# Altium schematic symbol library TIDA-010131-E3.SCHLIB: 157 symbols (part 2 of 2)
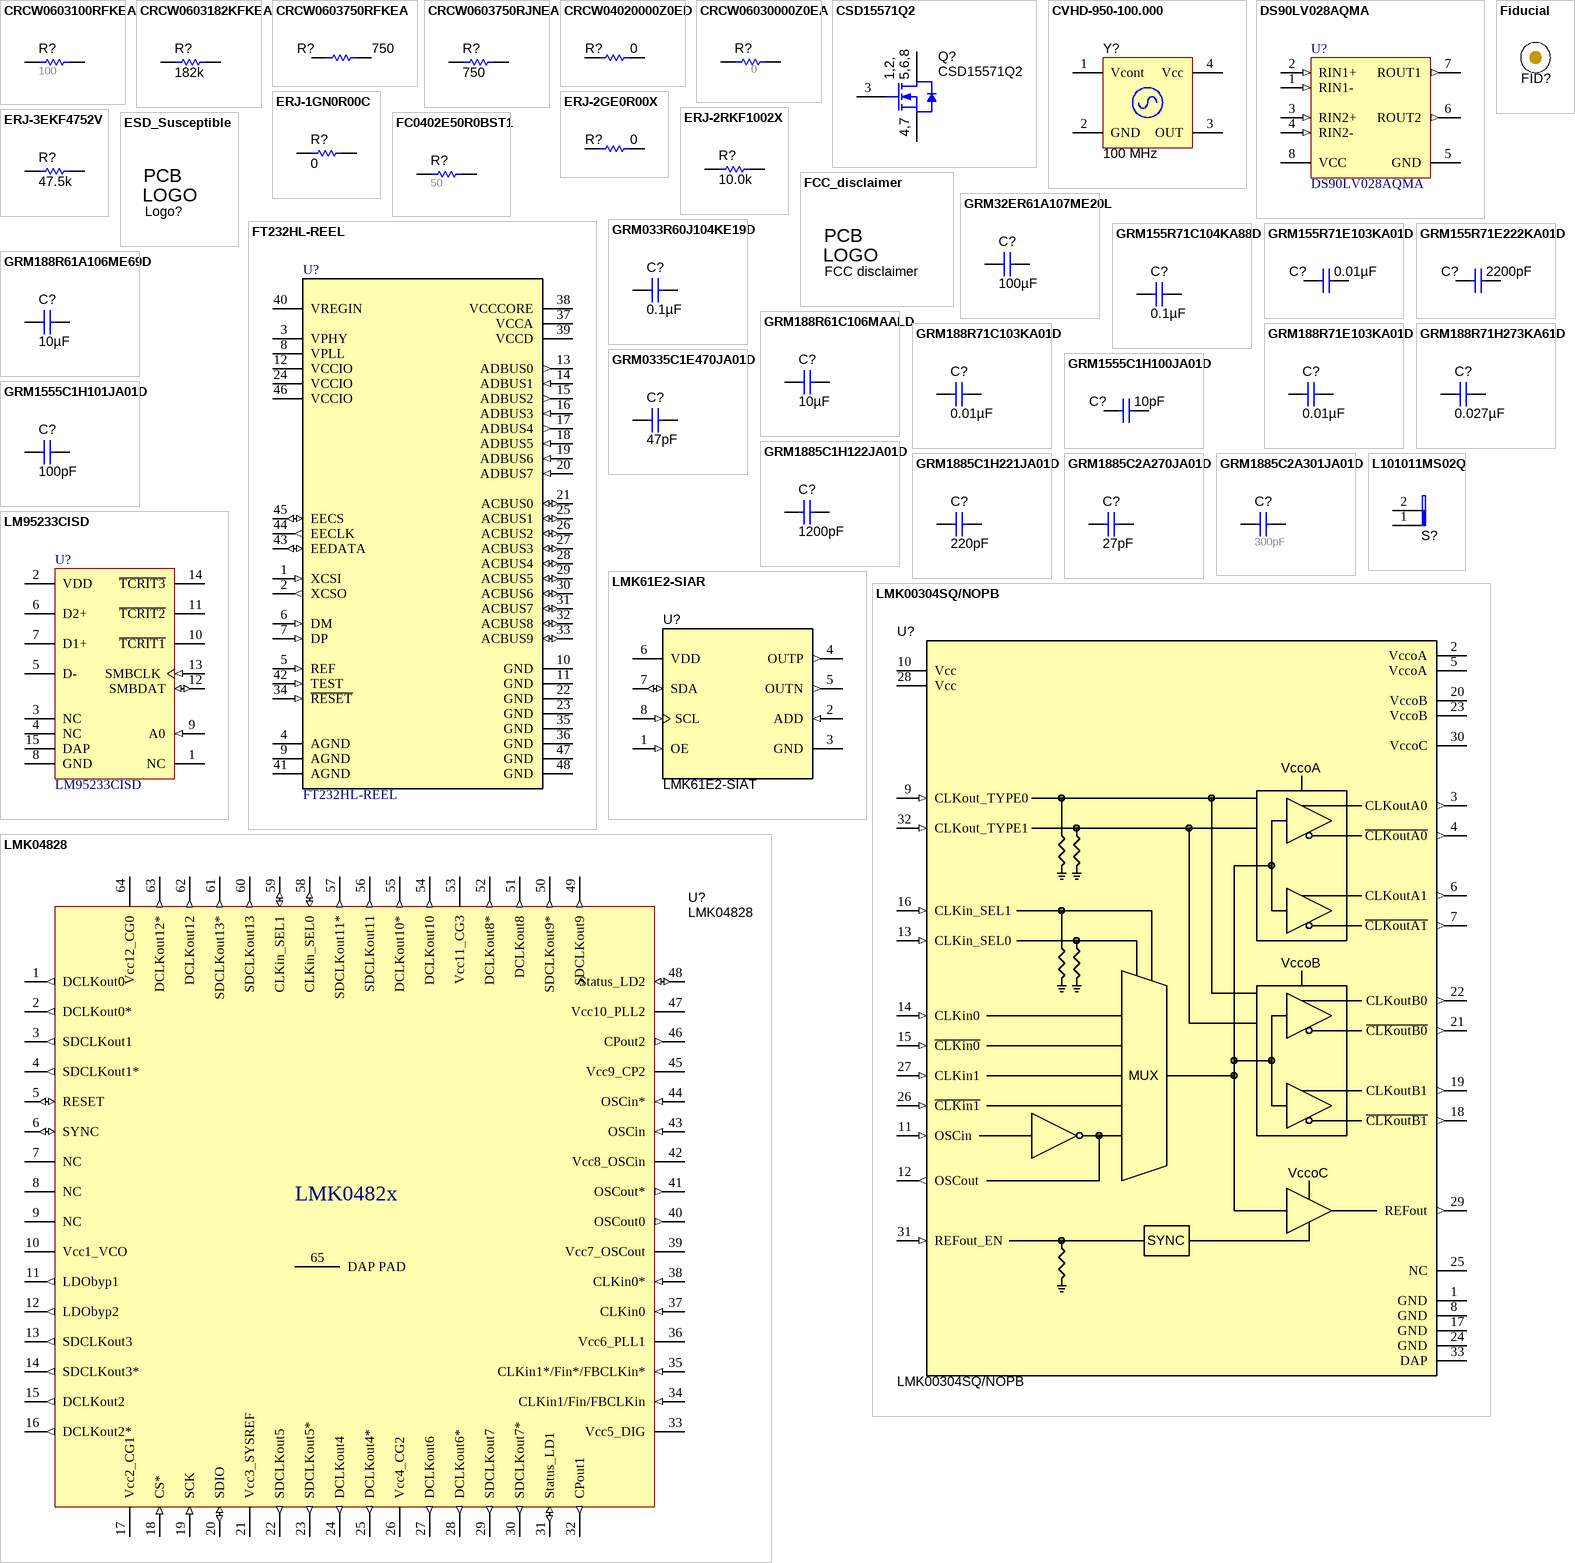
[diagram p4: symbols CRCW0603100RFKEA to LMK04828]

## GRM188R71E103KA01D
designator C?  ValueDisplayed: 0.01µF  (hidden comment: GRM188R71E103KA01D)
CAP, CERM, 0.01 µF, 25 V, +/- 10%, X7R, 0603; Manufacturer: MuRata; Polarized: N; CompType: Capacitor; Value: 0.01uF; U/M: EA; Cap_F: 0.00000001; Tolerance_%: 10; Value1: Unknown; VDC_V: 25; Value2: 25V; TaMin_C: -55; TaMax_C: 125; Cap_Case: 0603; SizeArea_mm2: 1.28; SizeAreaWB_mm2: 4.68; SizeX_mm: 1.6; SizeY_mm: 0.8; SizeZ_mm: 1; AEC Category: Q200
signal-integrity model Cap
simulation model Cap
footprint 0603
footprint 0603M
footprint 0603L
footprint 0603_HV
footprint 0603S
pins: 1, 2

## GRM188R71H273KA61D
designator C?  ValueDisplayed: 0.027µF  (hidden comment: GRM188R71H273KA61D)
CAP, CERM, 0.027 µF, 50 V, +/- 10%, X7R, 0603; Manufacturer: MuRata; Cap_Case: 0603; Polarized: N; TaMax_C: 125; TaMin_C: -55; Tolerance_%: 10; VDC_V: 50; Cap_F: 0.000000027; CompType: Capacitor; Value: 0.027uF; Value1: Unknown; Value2: 50V; U/M: EA; AEC Category: Q200; SizeArea_mm2: 1.28; SizeAreaWB_mm2: 4.68; SizeX_mm: 1.6; SizeY_mm: 0.8; SizeZ_mm: 1
signal-integrity model Cap
simulation model Cap
footprint 0603
footprint 0603M
footprint 0603L
footprint 0603_HV
footprint 0603S
pins: 1, 2

## GRM0335C1E470JA01D
designator C?  ValueDisplayed: 47pF  (hidden comment: GRM0335C1E470JA01D)
CAP, CERM, 47 pF, 25 V, +/- 5%, C0G/NP0, 0201; Manufacturer: MuRata; Polarized: N; CompType: Capacitor; Value: 47pF; U/M: EA; Cap_F: 0.000000000047; Tolerance_%: 5; Value1: Unknown; VDC_V: 25; Value2: 25V; TaMin_C: -55; TaMax_C: 125; Cap_Case: 0201; SizeArea_mm2: 0.18; SizeAreaWB_mm2: 2.08; SizeX_mm: 0.6; SizeY_mm: 0.3; SizeZ_mm: 0.33; AEC Category: Q200
signal-integrity model Cap
simulation model Cap
footprint 0201_033
footprint 0201_033M
footprint 0201_033L
pins: 1, 2

## GRM1555C1H100JA01D
designator C?  ValueDisplayed: 10pF  (hidden comment: GRM1555C1H100JA01D)
CAP, CERM, 10 pF, 50 V, +/- 5%, C0G/NP0, 0402; Manufacturer: MuRata; Polarized: N; CompType: Capacitor; Value: 10pF; U/M: EA; Cap_F: 0.00000000001; Tolerance_%: 5; Value1: Unknown; VDC_V: 50; Value2: 50V; TaMin_C: -55; TaMax_C: 125; Cap_Case: 0402; SizeArea_mm2: 0.5; SizeAreaWB_mm2: 3; SizeX_mm: 1; SizeZ_mm: 0.6; AEC Category: Q200
signal-integrity model Cap
simulation model Cap
footprint 0402
footprint 0402M
footprint 0402L
footprint 0402S
pins: 1, 2

## GRM1555C1H101JA01D
designator C?  ValueDisplayed: 100pF  (hidden comment: GRM1555C1H101JA01D)
CAP, CERM, 100 pF, 50 V, +/- 5%, C0G/NP0, 0402; Manufacturer: MuRata; Polarized: N; CompType: Capacitor; Value: 100pF; U/M: EA; Cap_F: 0.0000000001; Tolerance_%: 5; Value1: Unknown; VDC_V: 50; Value2: 50V; TaMin_C: -55; TaMax_C: 125; Cap_Case: 0402; SizeArea_mm2: 0.5; SizeAreaWB_mm2: 3; SizeX_mm: 1; SizeZ_mm: 0.6; AEC Category: Q200
signal-integrity model Cap
simulation model Cap
footprint 0402
footprint 0402M
footprint 0402L
footprint 0402S
pins: 1, 2

## GRM1885C1H122JA01D
designator C?  ValueDisplayed: 1200pF  (hidden comment: GRM1885C1H122JA01D)
CAP, CERM, 1200 pF, 50 V, +/- 5%, C0G/NP0, 0603; Manufacturer: MuRata; Cap_Case: 0603; Polarized: N; TaMax_C: 125; TaMin_C: -55; Tolerance_%: 5; VDC_V: 50; Cap_F: 0.0000000012; CompType: Capacitor; Value: 1200pF; Value1: Unknown; Value2: 50V; U/M: EA; SizeArea_mm2: 1.28; SizeAreaWB_mm2: 4.68; SizeX_mm: 1.6; SizeY_mm: 0.8; SizeZ_mm: 1; AEC Category: Q200
signal-integrity model Cap
simulation model Cap
footprint 0603
footprint 0603M
footprint 0603L
footprint 0603_HV
footprint 0603S
pins: 1, 2

## GRM1885C1H221JA01D
designator C?  ValueDisplayed: 220pF  (hidden comment: GRM1885C1H221JA01D)
CAP, CERM, 220 pF, 50 V, +/- 5%, C0G/NP0, 0603; Manufacturer: MuRata; Cap_Case: 0603; Polarized: N; TaMax_C: 125; TaMin_C: -55; Tolerance_%: 5; VDC_V: 50; Cap_F: 0.00000000022; CompType: Capacitor; Value: 220pF; Value1: Unknown; Value2: 50V; U/M: EA; AEC Category: Q200; SizeArea_mm2: 1.28; SizeAreaWB_mm2: 4.68; SizeX_mm: 1.6; SizeY_mm: 0.8; SizeZ_mm: 1
signal-integrity model Cap
simulation model Cap
footprint 0603
footprint 0603M
footprint 0603L
footprint 0603_HV
footprint 0603S
pins: 1, 2

## GRM1885C2A270JA01D
designator C?  ValueDisplayed: 27pF  (hidden comment: GRM1885C2A270JA01D)
CAP, CERM, 27 pF, 100 V, +/- 5%, C0G/NP0, 0603; Manufacturer: MuRata; Polarized: N; CompType: Capacitor; Value: 27pF; U/M: EA; Cap_F: 0.000000000027; Tolerance_%: 5; Value1: Unknown; VDC_V: 100; Value2: 100V; TaMin_C: -55; TaMax_C: 125; Cap_Case: 0603; SizeArea_mm2: 1.28; SizeAreaWB_mm2: 4.68; SizeX_mm: 1.6; SizeY_mm: 0.8; SizeZ_mm: 1; AEC Category: Q200
signal-integrity model Cap
simulation model Cap
footprint 0603
footprint 0603M
footprint 0603L
footprint 0603_HV
footprint 0603S
pins: 1, 2

## GRM1885C2A301JA01D
designator C?  ValueDisplayed: 300pF  (hidden comment: GRM1885C2A301JA01D)
CAP, CERM, 300pF, 100V, +/-5%, C0G/NP0, 0603; Manufacturer: MuRata; Cap_Case: 0603; Polarized: N; TaMax_C: 125; TaMin_C: -55; Tolerance_%: 5; VDC_V: 100; Cap_F: 0.0000000003; CompType: Capacitor; Value1: Unknown; U/M: EA
signal-integrity model Cap
simulation model Cap
footprint 0603
footprint 0603M
footprint 0603L
footprint 0603_HV
footprint 0603S
pins: 1, 2

## L101011MS02Q
designator S?  (value not drawn)
SWITCH SLIDE SPST 4A PCB, TH; Manufacturer: C&K Components; Symbol Creator: a0411947; VDC_V: 125; SwitchFunction: Off-On; PositionCount: 1; CurrentRating_mA: 4000
footprint SW_ L101011MS02Q (SWITCH SLIDE sPST 4A PCB)
pins: 1, 2

## LM95233CISD
designator U?
Dual Remote Diode and Local Temperature Sensor with SMBus Interface and TruTherm Technology, 15-pin LLP; Manufacturer: Texas Instruments; PackageTopMarking: NS*UZXYTT*95233CI; PowerWise: Y; CompType: Temp Sensor IC
footprint SDA14B (SON, 14-Leads, Body 4x4mm, Pitch 0.5mm, NSC Recommended)
pins: 1 NC, 2 VDD (power), 3 NC, 4 NC, 5 D-, 6 D2+, 7 D1+, 8 GND (power), 9 A0 (in), 10 ~{TCRIT1} (oc), 11 ~{TCRIT2} (oc), 12 SMBDAT (io), 13 SMBCLK (in), 14 ~{TCRIT3} (oc), 15 DAP (power)

## LMK61E2-SIAR
designator U?, comment LMK61E2-SIAT
Ultra-Low Jitter Programmable Oscillator with Internal EEPROM, SIA0008B; Manufacturer: Texas Instruments; SymbolCreator: Altium; CompType: IC; U/M: EA
footprint SIA0008B
pins: 1 OE (in), 2 ADD (in), 3 GND (power), 4 OUTP (out), 5 OUTN (out), 6 VDD (power), 7 SDA (io), 8 SCL (in)

## LMK00304SQ/NOPB
designator U?
3.1-GHz Differential Clock Buffer/Level Translator, RTV0032A (WQFN-32); Manufacturer: Texas Instruments; SymbolCreator: a0411947; SizeArea_mm2: 25; SizeAreaWB_mm2: 49; SizeX_mm: 5; SizeZ_mm: 0.8; CompType: IC; U/M: EA
footprint RTV0032A
pins: 1 GND (power), 2 VccoA (power), 3 CLKoutA0 (out), 4 ~{CLKoutA0} (out), 5 VccoA (power), 6 CLKoutA1 (out), 7 ~{CLKoutA1} (out), 8 GND (power), 9 CLKout_TYPE0 (in), 10 Vcc (power), 11 OSCin (in), 12 OSCout (out), 13 CLKin_SEL0 (in), 14 CLKin0 (in), 15 ~{CLKin0} (in), 16 CLKin_SEL1 (in), 17 GND (power), 18 ~{CLKoutB1} (out), 19 CLKoutB1 (out), 20 VccoB (power), 21 ~{CLKoutB0} (out), 22 CLKoutB0 (out), 23 VccoB (power), 24 GND (power), 25 NC, 26 ~{CLKin1} (in), 27 CLKin1 (in), 28 Vcc (power), 29 REFout (out), 30 VccoC (power), 31 REFout_EN (in), 32 CLKout_TYPE1 (in), 33 DAP (power)
1 alternate drawing of the same symbol

## LMK04828
designator U?
Manufacturer: Texas Instruments; PartNumber: LMK04828BISQ
footprint LLP64(NS_SQA64A)_HYBRID
footprint NKD0064A (QFN, 64-Leads, Body 9x9mm, Pitch 0.5mm)
pins: 1 DCLKout0 (out) "CG0", 2 DCLKout0* (out) "CG0", 3 SDCLKout1 (out) "CG0", 4 SDCLKout1* (out) "CG0", 5 RESET (io), 6 SYNC (io), 7 NC, 8 NC, 9 NC, 10 Vcc1_VCO (power) "VCC_VCO_LDO", 11 LDObyp1 (out), 12 LDObyp2 (out), 13 SDCLKout3 (out) "CG1", 14 SDCLKout3* (out) "CG1", 15 DCLKout2 (out) "CG1", 16 DCLKout2* (out) "CG1", 17 Vcc2_CG1 (power) "VCC_CG1", 18 CS* (in), 19 SCK (in) "CG2", 20 SDIO (io) "CG2", 21 Vcc3_SYSREF (power) "CG2", 22 SDCLKout5 (out) "CG2", 23 SDCLKout5* (out), 24 DCLKout4 (out) "VCC_Digital", 25 DCLKout4* (out), 26 Vcc4_CG2 (power), 27 DCLKout6 (out) "Status", 28 DCLKout6* (out), 29 SDCLKout7 (out), 30 SDCLKout7* (out), 31 Status_LD1 (io), 32 CPout1 (out), 33 Vcc5_DIG (power) "Status", 34 CLKin1/Fin/FBCLKin (in), 35 CLKin1*/Fin*/FBCLKin* (in) "VCC_CP1", 36 Vcc6_PLL1 (power), 37 CLKin0 (in), 38 CLKin0* (in) "VCC_OSCin", 39 Vcc7_OSCout (power), 40 OSCout0 (out), 41 OSCout* (out) "OSCout", 42 Vcc8_OSCin (power), 43 OSCin (in) "VCC_DIV", 44 OSCin* (in) "uWire", 45 Vcc9_CP2 (power) "Vcc_CP2", 46 CPout2 (out) "uWire", 47 Vcc10_PLL2 (power) "Vcc_PLL2", 48 Status_LD2 (io) "CG3", 49 SDCLKout9 (out) "CG3", 50 SDCLKout9* (out) "CG3", 51 DCLKout8 (out) "CG3", 52 DCLKout8* (out) "VCC_CG4", 53 Vcc11_CG3 (power) "CG4", 54 DCLKout10 (out) "CG4", 55 DCLKout10* (out) "CG4", 56 SDCLKout11 (out) "CG4", 57 SDCLKout11* (out) "VCC_CG5", 58 CLKin_SEL0 (io) "CG5", 59 CLKin_SEL1 (io) "CG5", 60 SDCLKout13 (out) "CG5", 61 SDCLKout13* (out) "CG5", 62 DCLKout12 (out) "Status", 63 DCLKout12* (out), 64 Vcc12_CG0 (power), 65 DAP PAD (power) "DAP"

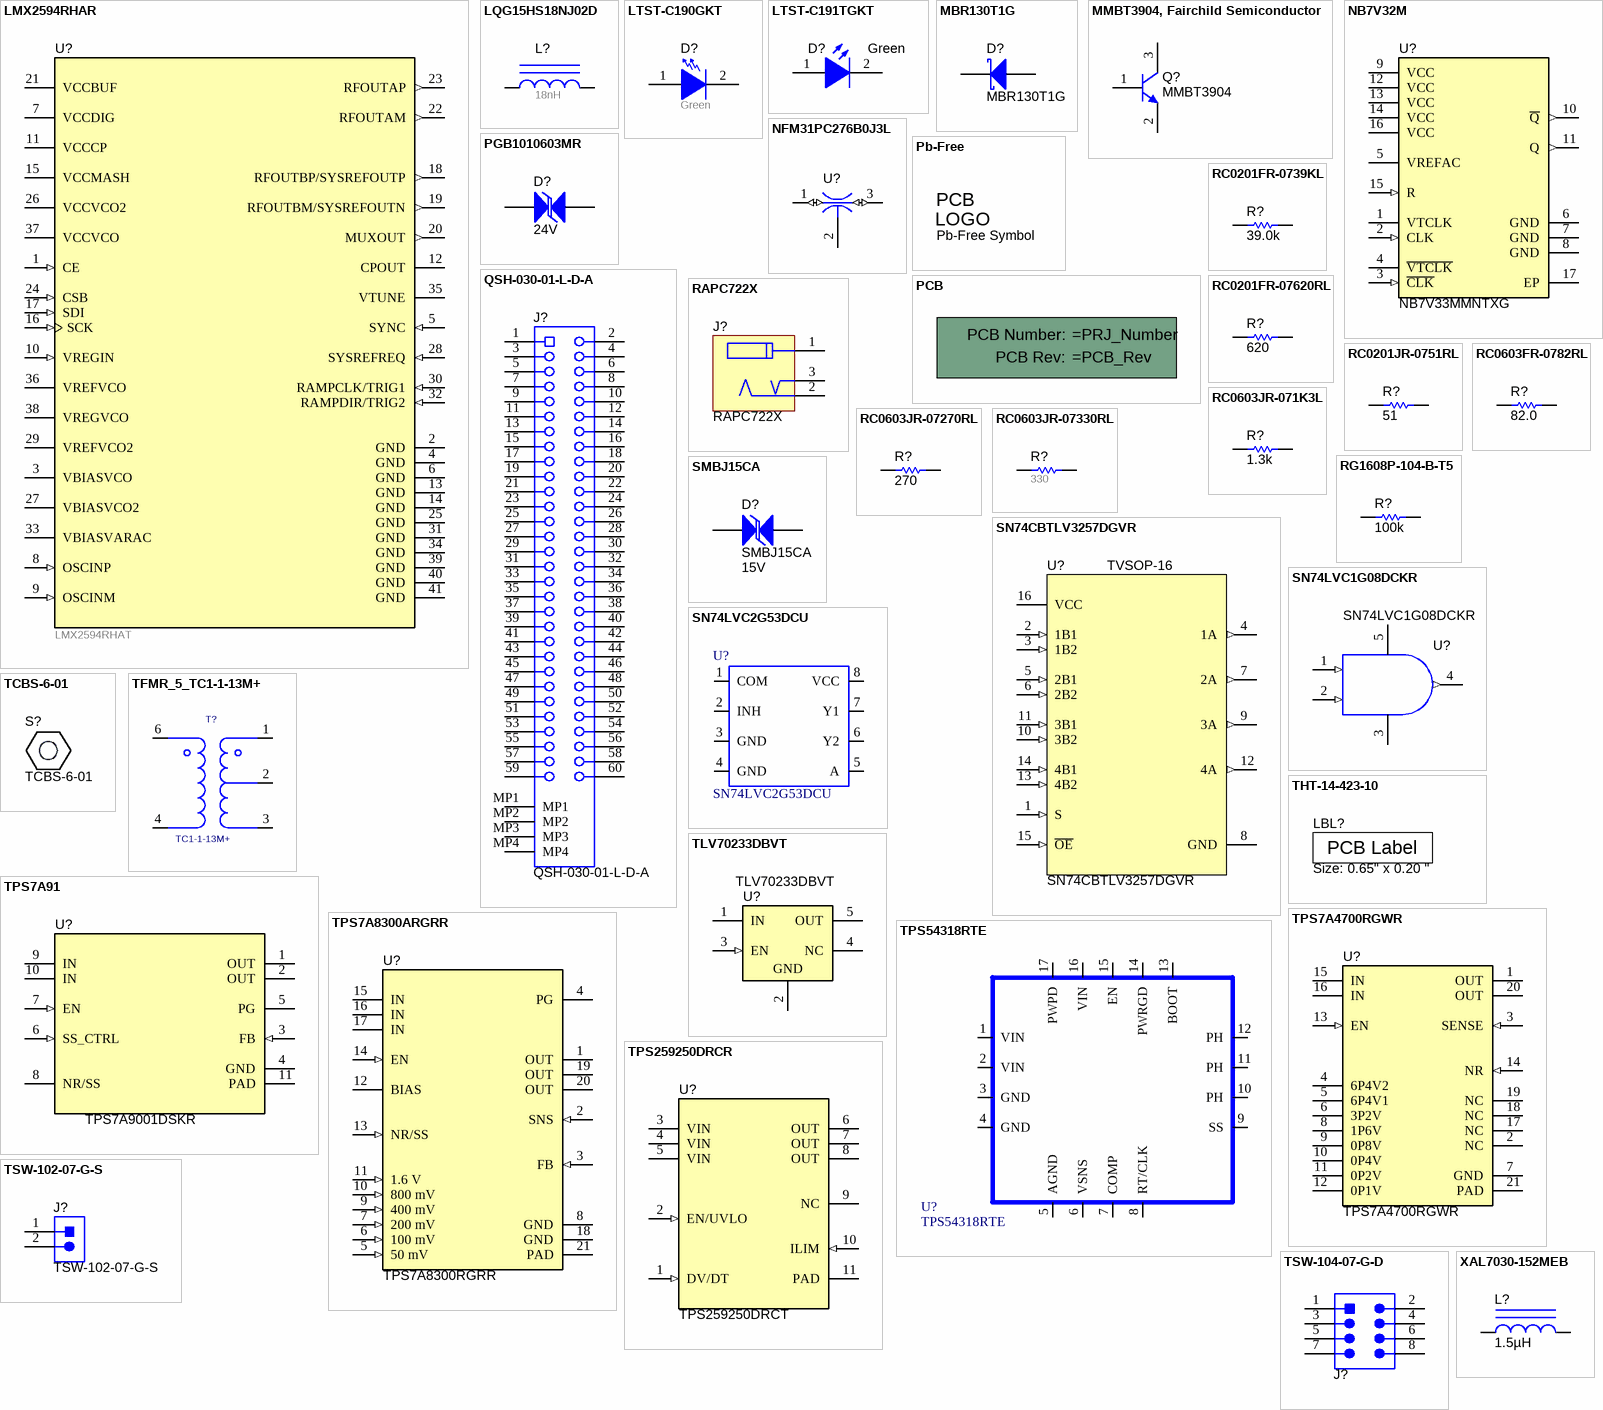
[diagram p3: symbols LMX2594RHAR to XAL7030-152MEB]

## LMX2594RHAR
designator U?, comment LMX2594RHAT
High Performance, Wideband PLLatinum RF Synthesizer, RHA0040A (VQFN-40); Manufacturer: Texas Instruments; SymbolCreator: Altium; SizeArea_mm2: 36; SizeAreaWB_mm2: 64; SizeX_mm: 6; SizeZ_mm: 1; CompType: IC; U/M: EA
footprint RHA0040A (QFN, 40-Leads, Body 6x6mm, Pitch 0.5mm, Thermal Pad 4.6x4.6mm, TI Recommended)
footprint RHA0040A_NV
footprint RHA0040C
pins: 1 CE (in), 2 GND (power), 3 VBIASVCO, 4 GND (power), 5 SYNC (in), 6 GND (power), 7 VCCDIG (power), 8 OSCINP (in), 9 OSCINM (in), 10 VREGIN (in), 11 VCCCP (power), 12 CPOUT, 13 GND (power), 14 GND (power), 15 VCCMASH (power), 16 SCK (in), 17 SDI (in), 18 RFOUTBP/SYSREFOUTP (out), 19 RFOUTBM/SYSREFOUTN (out), 20 MUXOUT (out), 21 VCCBUF (power), 22 RFOUTAM (out), 23 RFOUTAP (out), 24 CSB (in), 25 GND (power), 26 VCCVCO2 (power), 27 VBIASVCO2, 28 SYSREFREQ (in), 29 VREFVCO2, 30 RAMPCLK/TRIG1 (in), 31 GND (power), 32 RAMPDIR/TRIG2 (in), 33 VBIASVARAC, 34 GND (power), 35 VTUNE, 36 VREFVCO, 37 VCCVCO (power), 38 VREGVCO, 39 GND (power), 40 GND (power), 41 GND (power)

## LQG15HS18NJ02D
designator L?  ValueDisplayed: 18nH  (hidden comment: LQG15HS18NJ02D)
Inductor, Multilayer, Air Core, 18 nH, 0.3 A, 0.36 ohm, SMD; Manufacturer: MuRata; Value: 18nH; Ind_H: 18.0E-9; Imax_A: 0.3; Irms: 0.3A @ C rise; Isat: 0.3A @ % inductance drop; DCR_ohm: 0.36; Value2: 0.3A; AEC Category: Q200
signal-integrity model Inductor
simulation model Inductor
footprint IND_LQG15H
pins: 1, 2

## LTST-C190GKT
designator D?  value Green  (hidden comment: LTST-C190GKT)
LED, Green, SMD; Manufacturer: Lite-On; Vf_V: 2.1; Value2: 2.1V; Io_A: 0.02; Power_TotalModule: 0.1; Value1: 0.1W; U/M: EA
signal-integrity model Diode
footprint LED_LTST-C190
pins: 1 A, 2 K

## LTST-C191TGKT
designator D?  value Green  (hidden comment: LTST-C191TGKT)
LED, Green, SMD; Manufacturer: Lite-On; Type: InGaN; Vf_V: 3.2; Value2: 3.2V; Io_A: 0.02; Value1: W; U/M: EA
signal-integrity model Diode
footprint LTST-C191_Green
pins: 1 A, 2 K

## MBR130T1G
designator D?
Diode, Schottky, 30 V, 1 A, SOD-123; Manufacturer: ON Semiconductor; U/M: EA; Vf_V: 0.47; Value: 30V; Value1: 1A; Value2: 0.47V; Io_A: 1; Vr_V: 30; TJmax_C: 125; RJC_CperW: 108; SizeAreaWB_mm2: 13.095; SizeArea_mm2: 6.545; SizeX_mm: 3.85; SizeY_mm: 1.7; SizeZ_mm: 1.35; AEC Category: Q101
signal-integrity model Diode
simulation model mbr130prl
footprint SOD-123
pins: 1 K, 2 A

## MMBT3904, Fairchild Semiconductor
designator Q?, comment MMBT3904
Transistor, NPN, 40 V, 0.2 A, SOT-23; Manufacturer: Fairchild Semiconductor; CompType: BJT; PNP: 0; NPN: 1; Vceo_V: 40; Vcesat1_V: 0.2; Value: 40 V; Value1: 0.2 A; HfeMax: 300; TaMin_C: -55; TaMax_C: 150; SizeAreaWB_mm2: 14; SizeArea_mm2: 7.5; SizeX_mm: 2.5; SizeY_mm: 3; SizeZ_mm: 1.1; U/M: EA; AEC Category: Q101
footprint SOT-23
footprint SOT-23M
footprint SOT-23L
simulation model MMBT3904
pins: 1 B, 2 E, 3 C

## NB7V32M
designator U?, comment NB7V33MMNTXG
1.8V / 2.5V, 10GHz ÷4 Clock Divider with CML Outputs, QFN-16; Manufacturer: ON Semiconductor
footprint QFN16-3x3MM_0_5 (QFN, 16-Leads, Body 3x3mm, Pitch 0.5mm)
pins: 1 VTCLK, 2 CLK (in), 3 ~{CLK} (in), 4 ~{VTCLK}, 5 VREFAC (power), 6 GND (power), 7 GND (power), 8 GND (power), 9 VCC (power), 10 ~{Q} (out), 11 Q (out), 12 VCC (power), 13 VCC (power), 14 VCC (power), 15 R (in), 16 VCC (power), 17 EP (power)

## NFM31PC276B0J3L
designator U?  (value not drawn)
FILTER LC HIGH FREQ 27uF 1206; Manufacturer: MuRata; SymbolCreator: Altium
footprint Murata_NFM31P
pins: 1 (io), 2 (power), 3 (io)

## Pb-Free
designator Logo?, comment Pb-Free Symbol  (no BOM)
SymbolCreator: a0412235
footprint Pb-Free_Overlay_Medium
footprint Pb-Free_Overlay_Small

## PCB
designator !PCB?, comment Printed Circuit Board  (value not drawn)  (mechanical)
Manufacturer: Any; SymbolCreator: a0412235; CompType: PCB
1 alternate drawing of the same symbol

## PGB1010603MR
designator D?  value 24V  (hidden comment: PGB1010603MR)
PulseGuard ESD Suppressor, 24VDC, SMT; Manufacturer: Littelfuse
footprint PGB1_0603
pins: 1, 2

## QSH-030-01-L-D-A
designator J?
Receptacle, 0.5 mm, 30x2, Gold, TH; Manufacturer: Samtec; SymbolCreator: Altium; Pitch_mm: 0.5; Gender: Female; Shrouded: N; Row_Count: 2; RowSpacing_mm: 5.73
footprint Samtec_QSH-030-01-X-D-A
pins: 1, 2, 3, 4, 5, 6, 7, 8, 9, 10, 11, 12, 13, 14, 15, 16, 17, 18, 19, 20, 21, 22, 23, 24, 25, 26, 27, 28, 29, 30, 31, 32, 33, 34, 35, 36, 37, 38, 39, 40, 41, 42, 43, 44, 45, 46, 47, 48, 49, 50, 51, 52, 53, 54, 55, 56, 57, 58, 59, 60, MP1, MP2, MP3, MP4

## RAPC722X
designator J?
Power Jack, mini, 2.1mm OD, R/A, TH; Manufacturer: Switchcraft; SymbolCreator: a0799628
footprint CONN_RAPC722X
pins: 1, 2, 3

## RC0201FR-0739KL
designator R?  ValueDisplayed: 39.0k  (hidden comment: RC0201FR-0739KL)
RES, 39.0 k, 1%, 0.05 W, 0201; Manufacturer: Yageo America; CompType: Resistor; Value: 39.0k; Res_ohm: 39000; Value_Code: 39k0; Tolerance_%: 1; Power_W: 0.05; Value2: 0.05W; VDC_V: 25; TempCo: 200 ppm/C; SizeArea_mm2: 0.18; SizeX_mm: 0.6; SizeY_mm: 0.3; SizeZ_mm: 0.26; U/M: EA; AEC Category: Q200; AEC Qualified: N
signal-integrity model Resistor
simulation model Resistor
footprint 0201
footprint 0201M
footprint 0201L
footprint 0201_Silk
pins: 1, 2

## RC0201FR-07620RL
designator R?  ValueDisplayed: 620  (hidden comment: RC0201FR-07620RL)
RES, 620, 1%, 0.05 W, 0201; Manufacturer: Yageo America; CompType: Resistor; Value: 620; Value_Code: 620R; Tolerance_%: 1; Power_W: 0.05; Value2: 0.05W; VDC_V: 25; TempCo: 200 ppm/C; SizeArea_mm2: 0.18; SizeX_mm: 0.6; SizeY_mm: 0.3; SizeZ_mm: 0.26; U/M: EA; AEC Category: Q200; AEC Qualified: N
signal-integrity model Resistor
simulation model Resistor
footprint 0201
footprint 0201M
footprint 0201L
footprint 0201_Silk
pins: 1, 2

## RC0201JR-0751RL
designator R?  ValueDisplayed: 51  (hidden comment: RC0201JR-0751RL)
RES, 51, 5%, 0.05 W, 0201; Manufacturer: Yageo America; CompType: Resistor; Value: 51; Value_Code: 51R0; Tolerance_%: 5; Power_W: 0.05; Value2: 0.05W; VDC_V: 25; TempCo: 200 ppm/C; SizeArea_mm2: 0.18; SizeX_mm: 0.6; SizeY_mm: 0.3; SizeZ_mm: 0.26; EIA_Code: E24; U/M: EA; AEC Category: Q200; AEC Qualified: N
signal-integrity model Resistor
simulation model Resistor
footprint 0201
footprint 0201M
footprint 0201L
footprint 0201_Silk
pins: 1, 2

## RC0603FR-0782RL
designator R?  ValueDisplayed: 82.0  (hidden comment: RC0603FR-0782RL)
RES, 82.0, 1%, 0.1 W, 0603; Manufacturer: Yageo America; CompType: Resistor; Value: 82.0; Res_ohm: 82; Value_Code: 82R0; Tolerance_%: 1; Power_W: 0.1; Value2: 0.1W; VDC_V: 150; TempCo: 200 ppm/C; SizeArea_mm2: 1.28; SizeX_mm: 1.6; SizeY_mm: 0.8; U/M: EA; AEC Category: Q200
signal-integrity model Resistor
simulation model Resistor
footprint 0603
footprint 0603M
footprint 0603L
footprint 0603_HV
footprint 0603S
pins: 1, 2

## RC0603JR-071K3L
designator R?  ValueDisplayed: 1.3k  (hidden comment: RC0603JR-071K3L)
RES, 1.3 k, 5%, 0.1 W, 0603; Manufacturer: Yageo America; CompType: Resistor; Value: 1.3k; Res_ohm: 1300; Value_Code: 1k30; Tolerance_%: 5; Power_W: 0.1; Value2: 0.1W; VDC_V: 50; TempCo: 100 ppm/C; SizeArea_mm2: 1.28; SizeX_mm: 1.6; SizeY_mm: 0.8; SizeZ_mm: 1; EIA_Code: E24; U/M: EA; AEC Category: Q200
signal-integrity model Resistor
simulation model Resistor
footprint 0603
footprint 0603M
footprint 0603L
footprint 0603_HV
footprint 0603S
pins: 1, 2

## RC0603JR-07270RL
designator R?  ValueDisplayed: 270  (hidden comment: RC0603JR-07270RL)
RES, 270, 5%, 0.1 W, 0603; Manufacturer: Yageo America; CompType: Resistor; Tolerance_%: 5; VDC_V: 50; Power_W: 0.1; Value: 270; U/M: EA; Value_Code: 270R; Value2: 0.1W; TempCo: 100 ppm/C; EIA_Code: E24; SizeArea_mm2: 1.28; SizeX_mm: 1.6; SizeY_mm: 0.8; SizeZ_mm: 1; AEC Category: Q200
signal-integrity model Resistor
simulation model Resistor
footprint 0603
footprint 0603M
footprint 0603L
footprint 0603_HV
footprint 0603S
pins: 1, 2

## RC0603JR-07330RL
designator R?  value 330  (hidden comment: RC0603JR-07330RL)
RES, 330 ohm, 5%, 0.1W, 0603; Manufacturer: Yageo America; CompType: Resistor; Tolerance_%: 5; VDC_V: 50; Power_W: 0.1; U/M: EA; Value_Code: 330R; EIA_Code: E24
signal-integrity model Resistor
simulation model Resistor
footprint 0603
footprint 0603M
footprint 0603L
footprint 0603_HV
pins: 1, 2

## RG1608P-104-B-T5
designator R?  ValueDisplayed: 100k  (hidden comment: RG1608P-104-B-T5)
RES, 100 k, 0.1%, 0.1 W, 0603; Manufacturer: Susumu Co Ltd; CompType: Resistor; Value: 100k; Res_ohm: 100000; Tolerance_%: 0.1; Value2: 0.1W; VDC_V: 75; TempCo: 25 ppm/C; SizeArea_mm2: 1.28; SizeX_mm: 1.6; SizeY_mm: 0.8; SizeZ_mm: 1; EIA_Code: E192; U/M: EA; AEC Category: Q200
signal-integrity model Resistor
simulation model Resistor
footprint 0603
footprint 0603M
footprint 0603L
footprint 0603_HV
footprint 0603S
pins: 1, 2

## SMBJ15CA
designator D?  value 15V
Diode, TVS, Bi, 15 V, 24.4 Vc, SMB; Manufacturer: Fairchild Semiconductor; U/M: EA; Vr_V: 15; Value1: W; AEC Category: Q101
footprint SMB-Bi
pins: 1, 2

## SN74CBTLV3257DGVR
designator U?  PackageDescription: TVSOP-16
Low-Voltage 4-Bit 1-Of-2 FET Multiplexer/Demultiplexer, DGV0016A (TVSOP-16); Manufacturer: Texas Instruments; SymbolCreator: Altium; SizeArea_mm2: 40.96; SizeAreaWB_mm2: 70.56; SizeX_mm: 6.4; SizeZ_mm: 1.2; CompType: IC; U/M: EA
footprint DGV0016A_N
footprint DGV0016A_M
footprint DGV0016A_L
pins: 1 S (in), 2 1B1 (in), 3 1B2 (in), 4 1A (out), 5 2B1 (in), 6 2B2 (in), 7 2A (out), 8 GND (power), 9 3A (out), 10 3B2 (in), 11 3B1 (in), 12 4A (out), 13 4B2 (in), 14 4B1 (in), 15 ~{OE} (in), 16 VCC (power)

## SN74LVC1G08DCKR
designator U?
Single 2-Input Positive-AND Gate, DCK0005A (SOT-5); Alternate PartNumber: SN74LVC1G08DCKT; Manufacturer: Texas Instruments; CompType: IC; SizeArea_mm2: 4.2; SizeAreaWB_mm2: 9.3; SizeX_mm: 2.1; SizeY_mm: 2; SizeZ_mm: 1.1; U/M: EA
footprint DCK0005A_N
footprint DCK0005A_M
footprint DCK0005A_L
pins: 1 A (in), 2 B (in), 3 V- (power), 4 Y (out), 5 V+ (power)

## SN74LVC2G53DCU
designator U?
IC, SPDT Analog Switch; Manufacturer: TI; Alternate Manufacturer: None; Area: 36735
footprint VSSOP8
pins: 1 COM, 2 INH, 3 GND, 4 GND, 5 A, 6 Y2, 7 Y1, 8 VCC

## TCBS-6-01
designator S?
HEX STANDOFF SPACER, 9.53 mm; Manufacturer: Richco Plastics; SymbolCreator: a0412235
footprint TCBS-6-01

## TFMR_5_TC1-1-13M+
designator T?, comment TC1-1-13M+
Mfr_Name: Mini-Circuits; Mfr-_Part_Number: TC1-1-13MA+
footprint TFMR_5_150x150_50
footprint TFMR_5_150x150_50
pins: 1 secondary_dot, 2 secondary_ct, 3 secondary, 4 primary, 6 primary_dot

## THT-14-423-10
designator LBL?, comment Size: 0.65" x 0.20 "
Thermal Transfer Printable Labels, 0.650" W x 0.200" H - 10,000 per roll; Manufacturer: Brady; PartNumber: THT-14-423-10; SymbolCreator: a0412235; CompType: Label
footprint Label_650x200

## TLV70233DBVT
designator U?
Single Output LDO, 300 mA, Fixed 3.3 V Output, 2 to 5.5 V Input, with Low IQ, 5-pin SOT-23 (DBV), -40 to 125 degC, Green (RoHS & no Sb/Br); Manufacturer: Texas Instruments; Alternate PartNumber: Equivalent; Accuracy(%): 2; Fixed Output Options(V): 3.3; Iout(Max)(A): 0.3; Iq(Typ)(mA): 0.03; SubFamily: Single Channel LDO; Vdo(Typ)(mV): 220; Vin(Max)(V): 5.5
footprint DBV0005A_N (SOT23, 5-Leads, Body 2.9x1.6mm, Pitch 0.95mm, IPC Medium Density)
footprint DBV0005A_L (SOT23, 5-Leads, Body 2.9x1.6mm, Pitch 0.95mm, IPC High Density)
footprint DBV0005A_M (SOT23, 5-Leads, Body 2.9x1.6mm, Pitch 0.95mm, IPC Low Density)
pins: 1 IN (power) "Input supply voltage", 2 GND (power) "Ground", 3 EN (in) "Enable input", 4 NC "No connected", 5 OUT (power) "Regulated output voltage"

## TPS7A91
designator U?, comment TPS7A9001DSKR
500mA High-Accuracy Low-Noise Low-Dropout (LDO) Voltage Regulator, DSK0010A (WSON-10); Alternate PartNumber: TPS7A9001DSKT; Alternate Manufacturer: Texas Instruments; SizeAreaWB_mm2: 12.25; SizeZ_mm: 0.8; SizeX_mm: 2.5; SizeArea_mm2: 6.25; CompType: IC; AEC Qualified: N; AEC Category: Q200
footprint DSK0010A (SON, 10-Leads, Body 2.5x2.5mm, Pitch 0.5mm, Thermal Pad 2x1.2mm - ADI)
pins: 1 OUT (power), 2 OUT (power), 3 FB (in), 4 GND (power), 5 PG (oc), 6 SS_CTRL (in), 7 EN (in), 8 NR/SS, 9 IN (power), 10 IN (power), 11 PAD (power)

## TPS7A4700RGWR
designator U?
36-V, 1-A, 4.17-μVRMS, RF LDO Voltage Regulator, RGW0020A (VQFN-20); Alternate PartNumber: TPS7A4700RGWT; Manufacturer: Texas Instruments; SymbolCreator: a0412235; SizeArea_mm2: 25; SizeAreaWB_mm2: 49; SizeX_mm: 5; SizeZ_mm: 1; CompType: IC; U/M: EA
footprint RGW0020A
pins: 1 OUT (power), 2 NC, 3 SENSE (in), 4 6P4V2, 5 6P4V1, 6 3P2V, 7 GND (power), 8 1P6V, 9 0P8V, 10 0P4V, 11 0P2V, 12 0P1V, 13 EN (in), 14 NR (in), 15 IN (power), 16 IN (power), 17 NC, 18 NC, 19 NC, 20 OUT (power), 21 PAD

## TPS7A8300ARGRR
designator U?, comment TPS7A8300RGRR
2-A, 6-uVRMS, RF, LDO Voltage Regulator, RGR0020A (VQFN-20); Manufacturer: Texas Instruments; SymbolCreator: a0411947; SizeArea_mm2: 12.25; SizeAreaWB_mm2: 20.25; SizeX_mm: 3.5; SizeZ_mm: 1; CompType: IC; U/M: EA
footprint RGR0020A
footprint RGR0020A_NV
pins: 1 OUT (power), 2 SNS (in), 3 FB (in), 4 PG (oc), 5 50 mV (in), 6 100 mV (in), 7 200 mV (in), 8 GND (power), 9 400 mV (in), 10 800 mV (in), 11 1.6 V (in), 12 BIAS (power), 13 NR/SS (in), 14 EN (in), 15 IN (power), 16 IN (power), 17 IN (power), 18 GND (power), 19 OUT (power), 20 OUT (power), 21 PAD (power)

## TPS54318RTE
designator U?
IC, 2.95V To 6V Input, 3A Output, 2MHz, Synchronous SWIFT; Manufacturer: TI; Alternate Manufacturer: None; Area: 33865
footprint RTE-16
pins: 1 VIN, 2 VIN, 3 GND, 4 GND, 5 AGND, 6 VSNS, 7 COMP, 8 RT/CLK, 9 SS, 10 PH, 11 PH, 12 PH, 13 BOOT, 14 PWRGD, 15 EN, 16 VIN, 17 PWPD
1 alternate drawing of the same symbol

## TPS259250DRCR
designator U?, comment TPS259250DRCT
5V, 5A, 30mΩ eFuse with Adjustable +/-15% Accurate Current Limit, DRC0010J (VSON-10); Manufacturer: Texas Instruments; SymbolCreator: Altium; SizeArea_mm2: 9; SizeAreaWB_mm2: 16; SizeX_mm: 3; SizeZ_mm: 1; CompType: IC; U/M: EA
footprint DRC0010J
footprint DRC0010J_NV
pins: 1 DV/DT (in) "dV/dT", 2 EN/UVLO (in), 3 VIN (power), 4 VIN (power), 5 VIN (power), 6 OUT (power), 7 OUT (power), 8 OUT (power), 9 NC "BFET", 10 ILIM (in), 11 PAD (power)

## TSW-102-07-G-S
designator J?
Header, 100mil, 2x1, Gold, TH; Manufacturer: Samtec; SymbolCreator: a0412235; Pitch_mm: 2.54; Gender: Male; Shrouded: N; Row_Count: 1; Current_A: 6.3; Voltage_V: 550; Cert_CSA: Y
footprint TSW-102-07-G-S
footprint TSW-102-07-X-S
pins: 1, 2
1 alternate drawing of the same symbol

## TSW-104-07-G-D
designator J?  (value not drawn)
Header, 100mil, 4x2, Gold, TH; Manufacturer: Samtec; SymbolCreator: a0411947; Pitch_mm: 2.54; Gender: Male; Shrouded: N; Row_Count: 2; Current_A: 6.3; Voltage_V: 550; Cert_CSA: Y
footprint TSW-104-07-G-D
pins: 1, 2, 3, 4, 5, 6, 7, 8

## XAL7030-152MEB
designator L?  ValueDisplayed: 1.5µH  (hidden comment: XAL7030-152MEB)
Inductor, Shielded, Composite, 1.5 µH, 15 A, 0.0076 ohm, SMD; Manufacturer: Coilcraft; Value: 1.5uH; Ind_H: 1.5E-6; Imax_A: 15; Irms: 15A @ 40C rise; Isat: 23.5A @ 0.7% inductance drop; DCR_ohm: 0.0076; Value2: 15A; SizeAreaWB_mm2: 100; SizeArea_mm2: 64; SizeX_mm: 8; SizeZ_mm: 3.1; AEC Category: Q200
signal-integrity model Inductor
simulation model Inductor
footprint XAL7030 (Coilcraft XAL7030 7.5 x.7.5 x 3.1 mm)
pins: 1, 2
